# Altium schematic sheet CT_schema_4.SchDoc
size 298 x 247 mm
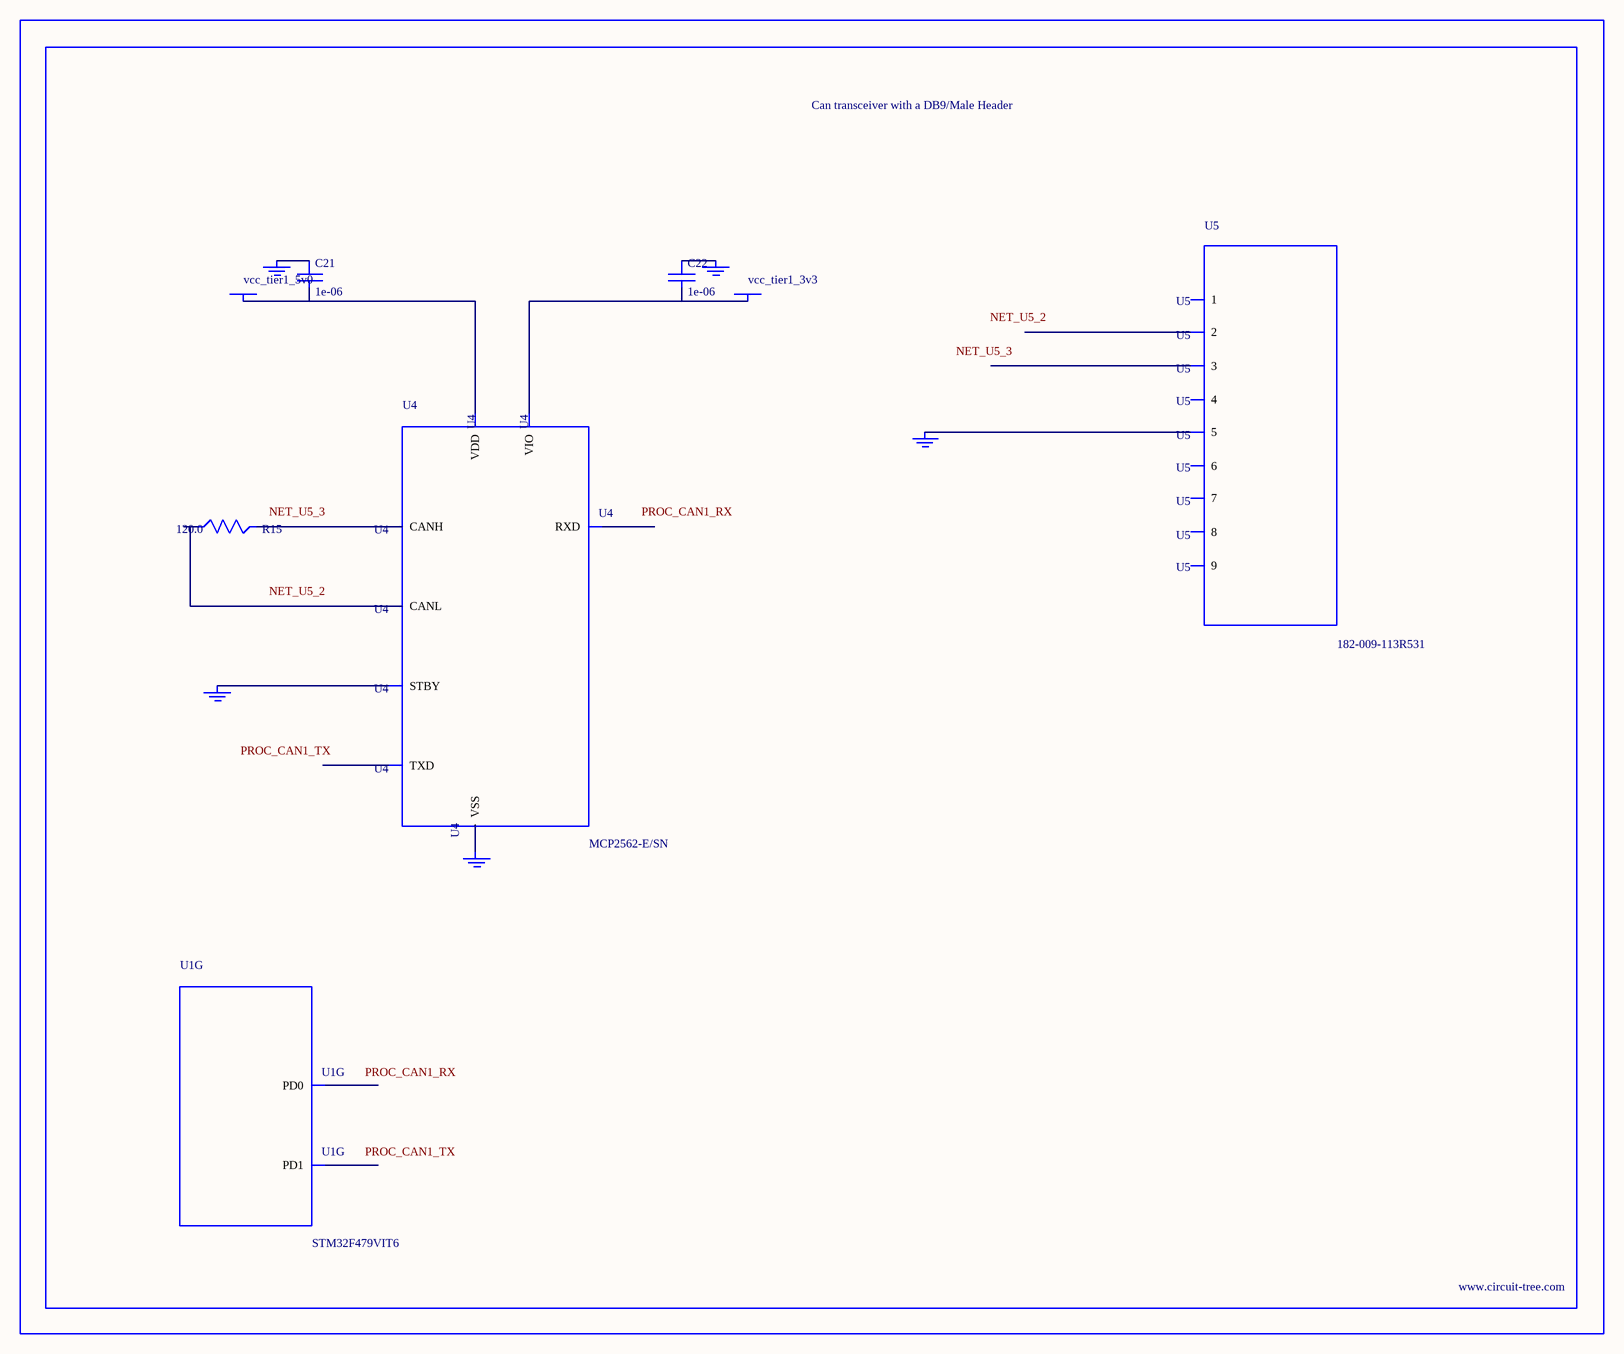
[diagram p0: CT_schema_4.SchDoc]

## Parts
BORDER3  (no value)
C21  1e-06  [C0603]
C22  1e-06  [C0603]
GND_INSTANCE_3_0  (no value)
GND_INSTANCE_3_1  (no value)
GND_INSTANCE_3_2  (no value)
GND_INSTANCE_3_3  (no value)
GND_INSTANCE_3_4  (no value)
POWER_INSTANCE_3_0  vcc_tier1_5v0
POWER_INSTANCE_3_1  vcc_tier1_3v3
R15  120.0  [R0603]
U1  STM32F479VIT6  [LQFP100]  (part G of 9)
U4  MCP2562-E/SN  [SOIC-8]
U5  182-009-113R531  [182-009-MALE]

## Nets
NetC21_1: C21.1 GND_INSTANCE_3_0.0(GND)
NetC21_2: C21.2 POWER_INSTANCE_3_0.0(PWR) U4.3(VDD)
NetC22_1: C22.1 GND_INSTANCE_3_1.0(GND)
NetC22_2: C22.2 POWER_INSTANCE_3_1.0(PWR) U4.5(VIO)
NetGND_INSTANCE_3_2_0: GND_INSTANCE_3_2.0(GND) U4.8(STBY)
NetGND_INSTANCE_3_3_0: GND_INSTANCE_3_3.0(GND) U4.2(VSS)
NetGND_INSTANCE_3_4_0: GND_INSTANCE_3_4.0(GND) U5.5
NetR15_1: R15.1 U4.6(CANL)
NetR15_2: R15.2 U4.7(CANH)

Not connected (* = marked no-connect by the designer): U1 84(PD0) 85(PD1); U4 1(TXD) 4(RXD); U5 1 2 3 4 6 7 8 9

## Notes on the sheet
- Labels drawn without touching a wire or pin: NET_U5_2, NET_U5_3, PROC_CAN1_RX, PROC_CAN1_TX

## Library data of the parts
BORDER3 = BORDER_PAGE3
C21 C22 = C0603C105K3RACTU
GND_INSTANCE_3_0-GND_INSTANCE_3_4 = GND
POWER_INSTANCE_3_0 POWER_INSTANCE_3_1 = PWR
R15 = RC0603JR-07120RL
